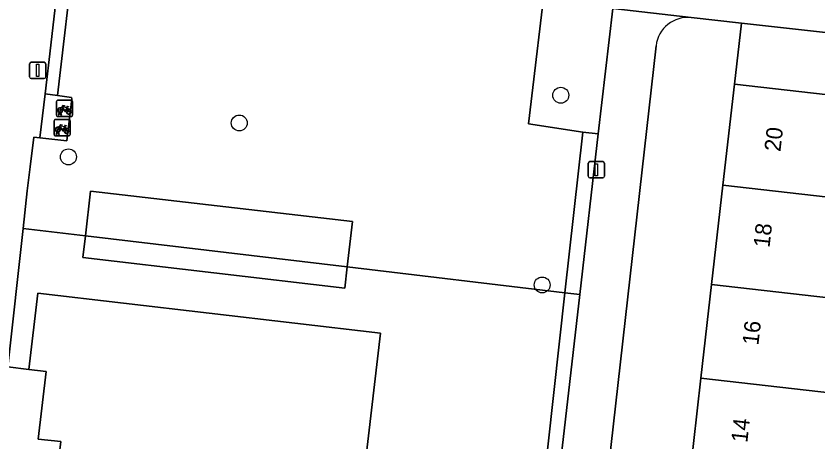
# Model space of a CAD drawing. Extents: x 161928 to 163071, y 386474 to 387428.
# Drawn here: x 162128.65 to 162177.94, y 386895.27 to 386921.48 of the extents above; entities that cross this region are included whole.
import ezdxf

# ---------------------------------------------------------------- set-up
doc = ezdxf.new("R2010")
doc.units = 0
for name, color, linetype in [('IMGEO_Boom', 7, 'Continuous'), ('IMGEO_Erf', 7, 'Continuous'), ('IMGEO_Fietsenrek', 7, 'Continuous'), ('IMGEO_Grasland_overig', 7, 'Continuous'), ('IMGEO_Groenvoorziening', 7, 'Continuous'), ('IMGEO_Haag', 7, 'Continuous'), ('IMGEO_Lichtmast', 7, 'Continuous'), ('IMGEO_Pand', 7, 'Continuous'), ('IMGEO_Pand_nummerreeks', 7, 'Continuous'), ('IMGEO_Voetpad_open', 7, 'Continuous')]:
    doc.layers.add(name, color=color, linetype=linetype)

msp = doc.modelspace()

# ---------------------------------------------------------------- linework, layer by layer
at = {"layer": 'IMGEO_Boom'}
for centre in [(162162.13, 386916.601), (162142.368, 386914.897), (162131.866, 386912.808), (162160.984, 386904.931)]:
    msp.add_circle(centre, 0.489, dxfattribs=at)
at = {"layer": 'IMGEO_Erf'}
for points in [[(162178.145, 386892.243), (162177.468, 386886.293), (162176.791, 386880.355), (162176.113, 386874.398), (162175.429, 386868.392), (162178.471, 386868.046), (162177.791, 386862.073), (162177.053, 386855.599), (162174.012, 386855.945), (162174.062, 386856.392), (162165.974, 386857.313), (162166.661, 386863.341), (162167.341, 386869.313), (162168.025, 386875.319), (162168.703, 386881.276), (162169.38, 386887.214), (162170.057, 386893.164), (162170.745, 386899.199), (162171.4, 386904.956), (162172.097, 386911.072), (162172.805, 386917.288), (162173.232, 386921.042), (162170.154, 386921.384)], [(162167.991, 386919.646), (162162.731, 386872.945), (162160.799, 386855.786)]]:
    msp.add_lwpolyline(points, dxfattribs=at)
msp.add_arc((162169.947, 386919.427), 1.968, 83.9549, 173.6098, dxfattribs=at)
at = {"layer": 'IMGEO_Fietsenrek'}
for p, q in [((162131.124, 386915.367), (162131.124, 386916.208)), ((162131.124, 386916.208), (162131.124, 386915.367)), ((162131.199, 386916.292), (162132.04, 386916.292)), ((162132.04, 386916.292), (162131.199, 386916.292)), ((162132.124, 386916.217), (162132.124, 386915.376)), ((162132.124, 386915.376), (162132.124, 386916.217)), ((162131.251, 386915.376), (162131.29, 386915.536)), ((162131.32, 386915.524), (162131.285, 386915.376)), ((162131.362, 386915.548), (162131.361, 386915.552)), ((162131.403, 386915.376), (162131.369, 386915.518)), ((162131.393, 386915.559), (162131.394, 386915.552)), ((162131.401, 386915.522), (162131.436, 386915.376)), ((162131.811, 386915.841), (162131.847, 386915.746)), ((162130.981, 386914.186), (162130.981, 386915.027)), ((162130.981, 386915.027), (162130.981, 386914.186)), ((162131.056, 386915.111), (162131.897, 386915.111)), ((162131.897, 386915.111), (162131.056, 386915.111)), ((162132.049, 386915.292), (162131.208, 386915.292)), ((162131.208, 386915.292), (162132.049, 386915.292)), ((162131.285, 386915.376), (162131.251, 386915.376)), ((162131.436, 386915.376), (162131.403, 386915.376)), ((162131.981, 386915.036), (162131.981, 386914.195)), ((162131.981, 386914.195), (162131.981, 386915.036)), ((162131.668, 386914.66), (162131.704, 386914.565)), ((162131.906, 386914.111), (162131.065, 386914.111)), ((162131.065, 386914.111), (162131.906, 386914.111)), ((162131.108, 386914.195), (162131.147, 386914.355)), ((162131.142, 386914.195), (162131.108, 386914.195)), ((162131.177, 386914.343), (162131.142, 386914.195)), ((162131.219, 386914.367), (162131.218, 386914.371)), ((162131.26, 386914.195), (162131.226, 386914.337)), ((162131.25, 386914.378), (162131.251, 386914.371)), ((162131.258, 386914.341), (162131.293, 386914.195)), ((162131.293, 386914.195), (162131.26, 386914.195))]:
    msp.add_line(p, q, dxfattribs=at)
for points in [[(162131.437, 386915.818), (162131.532, 386915.982), (162131.618, 386915.968), (162131.62, 386915.959), (162131.564, 386915.948), (162131.537, 386915.903), (162131.793, 386915.862)], [(162131.793, 386915.862), (162131.818, 386915.911), (162131.812, 386915.915), (162131.789, 386915.919), (162131.777, 386915.926), (162131.776, 386915.929), (162131.778, 386915.934), (162131.873, 386915.919), (162131.875, 386915.909), (162131.865, 386915.896), (162131.853, 386915.89), (162131.839, 386915.896), (162131.811, 386915.841)], [(162131.458, 386915.766), (162131.406, 386915.676), (162131.366, 386915.651), (162131.367, 386915.698), (162131.422, 386915.792)], [(162131.733, 386915.574), (162131.683, 386915.574), (162131.492, 386915.825), (162131.473, 386915.793)], [(162131.78, 386915.837), (162131.523, 386915.878), (162131.506, 386915.849), (162131.673, 386915.629), (162131.78, 386915.837)], [(162131.828, 386915.739), (162131.798, 386915.816), (162131.689, 386915.598), (162131.732, 386915.598)], [(162131.762, 386915.598), (162131.882, 386915.597), (162131.838, 386915.711)], [(162131.858, 386915.718), (162131.913, 386915.573), (162131.763, 386915.573)], [(162131.315, 386914.585), (162131.263, 386914.495), (162131.223, 386914.47), (162131.224, 386914.517), (162131.279, 386914.611)], [(162131.294, 386914.637), (162131.389, 386914.801), (162131.475, 386914.787), (162131.477, 386914.778), (162131.421, 386914.767), (162131.394, 386914.722), (162131.65, 386914.681)], [(162131.59, 386914.393), (162131.54, 386914.393), (162131.349, 386914.644), (162131.33, 386914.612)], [(162131.637, 386914.656), (162131.38, 386914.697), (162131.363, 386914.668), (162131.53, 386914.448), (162131.637, 386914.656)], [(162131.685, 386914.558), (162131.655, 386914.635), (162131.546, 386914.417), (162131.589, 386914.417)], [(162131.619, 386914.417), (162131.739, 386914.416), (162131.695, 386914.53)], [(162131.715, 386914.537), (162131.77, 386914.392), (162131.62, 386914.392)], [(162131.65, 386914.681), (162131.675, 386914.73), (162131.669, 386914.734), (162131.646, 386914.738), (162131.634, 386914.745), (162131.633, 386914.748), (162131.635, 386914.753), (162131.73, 386914.738), (162131.732, 386914.728), (162131.722, 386914.715), (162131.71, 386914.709), (162131.696, 386914.715), (162131.668, 386914.66)]]:
    msp.add_lwpolyline(points, dxfattribs=at)
for centre, radius, start, end in [((162131.202, 386916.214), 0.0779, 92.4484, 184.2845), ((162131.202, 386916.214), 0.0779, 92.4484, 184.2845), ((162132.046, 386916.214), 0.0779, 2.4484, 94.2845), ((162132.046, 386916.214), 0.0779, 2.4484, 94.2845), ((162131.364, 386915.677), 0.159, 62.6766, 242.1369), ((162131.364, 386915.677), 0.129, 63.3192, 238.903), ((162131.344, 386915.548), 0.0499, 12.8025, 158.6934), ((162131.364, 386915.677), 0.159, 253.9967, 271.7867), ((162131.344, 386915.548), 0.0174, 12.8025, 163.4502), ((162131.364, 386915.677), 0.129, 253.415, 269.0204), ((162131.364, 386915.677), 0.129, 283.6043, 43.4302), ((162131.364, 386915.677), 0.159, 283.5766, 46.6042), ((162131.891, 386915.593), 0.159, 113.3408, 178.3217), ((162131.891, 386915.593), 0.159, 187.0065, 105.7708), ((162131.891, 386915.593), 0.129, 113.923, 177.9556), ((162131.891, 386915.593), 0.129, 188.6715, 104.5883), ((162131.059, 386915.033), 0.0779, 92.4484, 184.2845), ((162131.059, 386915.033), 0.0779, 92.4484, 184.2845), ((162131.202, 386915.37), 0.0779, 182.4484, 274.2845), ((162131.202, 386915.37), 0.0779, 182.4484, 274.2845), ((162131.903, 386915.033), 0.0779, 2.4484, 94.2845), ((162131.903, 386915.033), 0.0779, 2.4484, 94.2845), ((162132.046, 386915.37), 0.0779, 272.4484, 4.2845), ((162132.046, 386915.37), 0.0779, 272.4484, 4.2845), ((162131.221, 386914.496), 0.159, 62.6766, 242.1369), ((162131.221, 386914.496), 0.129, 63.3192, 238.903), ((162131.201, 386914.367), 0.0499, 12.8025, 158.6934), ((162131.221, 386914.496), 0.129, 283.6043, 43.4302), ((162131.221, 386914.496), 0.159, 283.5766, 46.6042), ((162131.748, 386914.412), 0.159, 113.3408, 178.3217), ((162131.748, 386914.412), 0.159, 187.0065, 105.7708), ((162131.748, 386914.412), 0.129, 113.923, 177.9556), ((162131.748, 386914.412), 0.129, 188.6715, 104.5883), ((162131.059, 386914.189), 0.0779, 182.4484, 274.2845), ((162131.059, 386914.189), 0.0779, 182.4484, 274.2845), ((162131.221, 386914.496), 0.159, 253.9967, 271.7867), ((162131.201, 386914.367), 0.0174, 12.8025, 163.4502), ((162131.221, 386914.496), 0.129, 253.415, 269.0204), ((162131.903, 386914.189), 0.0779, 272.4484, 4.2845), ((162131.903, 386914.189), 0.0779, 272.4484, 4.2845)]:
    msp.add_arc(centre, radius, start, end, dxfattribs=at)
at = {"layer": 'IMGEO_Grasland_overig'}
msp.add_lwpolyline([(162132.908, 386907.956), (162132.751, 386906.613), (162148.846, 386904.735), (162148.998, 386906.039)], close=True, dxfattribs=at)
at = {"layer": 'IMGEO_Groenvoorziening'}
for points in [[(162132.921, 386938.209), (162130.783, 386919.684), (162130.438, 386916.685), (162131.185, 386916.594), (162133.279, 386934.481), (162133.619, 386937.387), (162135.792, 386937.148), (162142.971, 386936.185), (162143.068, 386937.049)], [(162161.306, 386924.662), (162148.537, 386926.392), (162148.883, 386929.792), (162142.351, 386930.715), (162142.971, 386936.185), (162135.792, 386937.148), (162133.619, 386937.387), (162133.279, 386934.481), (162131.185, 386916.594), (162132.064, 386916.471), (162132.076, 386916.378), (162131.773, 386913.806), (162130.104, 386913.982), (162129.743, 386914.02), (162129.521, 386912.206), (162129.329, 386910.72), (162129.078, 386908.413), (162132.908, 386907.956), (162133.229, 386910.707), (162149.324, 386908.828), (162148.998, 386906.039), (162162.387, 386904.444), (162163.488, 386914.329), (162160.154, 386914.845)], [(162165.657, 386924.87), (162166.468, 386931.931), (162162.332, 386932.43), (162161.306, 386924.662), (162160.154, 386914.845), (162163.488, 386914.329), (162164.435, 386914.228), (162165.32, 386921.935)], [(162172.805, 386917.288), (162180.893, 386916.367), (162189.178, 386915.439), (162191.787, 386915.141), (162192.218, 386918.931), (162173.232, 386921.042)], [(162164.435, 386914.228), (162163.488, 386914.329), (162162.387, 386904.444), (162163.299, 386904.335)], [(162149.324, 386908.828), (162133.229, 386910.707), (162132.908, 386907.956), (162148.998, 386906.039)], [(162162.387, 386904.444), (162148.998, 386906.039), (162148.846, 386904.735), (162132.751, 386906.613), (162132.908, 386907.956), (162129.078, 386908.413), (162128.148, 386899.89), (162129.432, 386899.739), (162129.979, 386904.421), (162151.04, 386901.963), (162148.87, 386883.371), (162148.652, 386883.397), (162148.215, 386879.856), (162151.904, 386879.625), (162152.206, 386882.013), (162156.805, 386881.426), (162157.588, 386889.1), (162160.649, 386888.845)]]:
    msp.add_lwpolyline(points, close=True, dxfattribs=at)
msp.add_lwpolyline([(162160.514, 386880.088), (162163.299, 386904.335), (162162.387, 386904.444), (162160.649, 386888.845)], dxfattribs=at)
at = {"layer": 'IMGEO_Haag'}
msp.add_lwpolyline([(162132.921, 386938.209), (162130.783, 386919.684), (162130.438, 386916.685), (162131.185, 386916.594), (162133.279, 386934.481), (162133.619, 386937.387), (162135.792, 386937.148), (162142.971, 386936.185), (162143.068, 386937.049)], close=True, dxfattribs=at)
at = {"layer": 'IMGEO_Lichtmast'}
for p, q in [((162129.477, 386917.731), (162129.477, 386918.531)), ((162129.477, 386918.531), (162129.477, 386917.731)), ((162129.577, 386918.631), (162130.367, 386918.631)), ((162130.367, 386918.631), (162129.577, 386918.631)), ((162130.467, 386918.531), (162130.467, 386917.731)), ((162130.467, 386917.731), (162130.467, 386918.531)), ((162130.367, 386917.631), (162129.577, 386917.631)), ((162129.577, 386917.631), (162130.367, 386917.631)), ((162163.92, 386912.516), (162164.71, 386912.516)), ((162164.71, 386912.516), (162163.92, 386912.516)), ((162163.82, 386911.616), (162163.82, 386912.416)), ((162163.82, 386912.416), (162163.82, 386911.616)), ((162164.81, 386912.416), (162164.81, 386911.616)), ((162164.81, 386911.616), (162164.81, 386912.416)), ((162164.71, 386911.516), (162163.92, 386911.516)), ((162163.92, 386911.516), (162164.71, 386911.516))]:
    msp.add_line(p, q, dxfattribs=at)
for points in [[(162129.897, 386918.506), (162130.047, 386918.506), (162130.047, 386917.756), (162129.897, 386917.756), (162129.897, 386918.506)], [(162164.24, 386912.391), (162164.39, 386912.391), (162164.39, 386911.641), (162164.24, 386911.641), (162164.24, 386912.391)]]:
    msp.add_lwpolyline(points, dxfattribs=at)
for centre, start, end in [((162129.577, 386918.531), 90, 180), ((162129.577, 386918.531), 90, 180), ((162130.367, 386918.531), 0, 90), ((162130.367, 386918.531), 360, 90), ((162129.577, 386917.731), 180, 270), ((162129.577, 386917.731), 180, 270), ((162130.367, 386917.731), 270, 0), ((162130.367, 386917.731), 270, 0), ((162163.92, 386912.416), 90, 180), ((162163.92, 386912.416), 90, 180), ((162164.71, 386912.416), 0, 90), ((162164.71, 386912.416), 360, 90), ((162163.92, 386911.616), 180, 270), ((162163.92, 386911.616), 180, 270), ((162164.71, 386911.616), 270, 0), ((162164.71, 386911.616), 270, 0)]:
    msp.add_arc(centre, 0.1, start, end, dxfattribs=at)
at = {"layer": 'IMGEO_Pand'}
for points in [[(162180.185, 386910.15), (162180.893, 386916.367), (162172.805, 386917.288), (162172.097, 386911.072)], [(162179.488, 386904.034), (162180.185, 386910.15), (162172.097, 386911.072), (162171.4, 386904.956)], [(162171.4, 386904.956), (162170.745, 386899.199), (162178.833, 386898.277), (162179.488, 386904.034)], [(162130.489, 386899.615), (162130.002, 386895.453), (162131.392, 386895.29), (162130.932, 386891.356), (162128.487, 386891.641), (162127.809, 386885.83), (162128.843, 386885.709), (162134.817, 386885.012), (162141.866, 386884.189), (162148.266, 386883.442), (162148.652, 386883.397), (162148.87, 386883.371), (162151.04, 386901.963), (162129.979, 386904.421), (162129.432, 386899.739)], [(162178.145, 386892.243), (162178.833, 386898.277), (162170.745, 386899.199), (162170.057, 386893.164)]]:
    msp.add_lwpolyline(points, close=True, dxfattribs=at)
at = {"layer": 'IMGEO_Voetpad_open'}
for points in [[(162130.932, 386891.356), (162131.392, 386895.29), (162130.002, 386895.453), (162130.489, 386899.615), (162129.432, 386899.739), (162128.148, 386899.89), (162129.078, 386908.413), (162129.329, 386910.72), (162129.521, 386912.206), (162129.743, 386914.02), (162130.104, 386913.982), (162130.438, 386916.685), (162130.783, 386919.684), (162132.921, 386938.209), (162129.774, 386938.593), (162128.658, 386928.695), (162128.956, 386928.662), (162128.272, 386922.439)], [(162169.498, 386924.436), (162165.657, 386924.87), (162165.32, 386921.935), (162170.154, 386921.384), (162173.232, 386921.042), (162192.218, 386918.931), (162194.106, 386918.722), (162213.884, 386916.523)], [(162170.154, 386921.384), (162165.32, 386921.935), (162164.435, 386914.228), (162163.299, 386904.335), (162160.514, 386880.088), (162160.501, 386879.997), (162160.06, 386875.774), (162160.048, 386875.599), (162159.784, 386873.278), (162162.731, 386872.945), (162167.991, 386919.646)]]:
    msp.add_lwpolyline(points, dxfattribs=at)
msp.add_lwpolyline([(162130.438, 386916.685), (162130.104, 386913.982), (162131.773, 386913.806), (162132.076, 386916.378), (162132.064, 386916.471), (162131.185, 386916.594)], close=True, dxfattribs=at)
msp.add_arc((162169.947, 386919.427), 1.968, 83.9549, 173.6098, dxfattribs=at)

# ---------------------------------------------------------------- texts
at = {"layer": 'IMGEO_Pand_nummerreeks'}
for s, p in [('20', (162175.63, 386913.1)), ('18', (162174.957, 386907.193)), ('16', (162174.274, 386901.192)), ('14', (162173.591, 386895.195))]:
    msp.add_text(s, height=1, rotation=83.5022, dxfattribs=at).set_placement(p)

doc.saveas('drawing.dxf')
